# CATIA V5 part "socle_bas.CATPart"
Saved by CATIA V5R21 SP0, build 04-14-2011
Part number: socle_bas
Revision: A
Nomenclature: 2
Material "Blanc": density 7860 kg/m3, Young's modulus 2e+11 Pa, Poisson ratio 0.266
Bounding box of the stored display mesh (mm): x -22 to 22, y -42.5 to 42.5, z -36 to 0
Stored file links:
  C:\Users\Olivier\Desktop\redaction CATIA (local)\CATIA\DONNEES\Exercice assemblage 1 (chassis et socle)\socle_bas.CATPart
  C:\Program Files\Dassault Systemes\B21\win_b64\startup\materials\French\Catalog.CATMaterial
  C:\Users\Olivier\Desktop\redaction CATIA (local)\pompe à moteur de ventilation refait\Pompe_a_moteur_de_ventilation.CATProduct
  C:\Users\Olivier\Desktop\redaction CATIA (local)\pompe à moteur de ventilation refait\Ecrou a collerette M5.CATPart
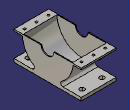
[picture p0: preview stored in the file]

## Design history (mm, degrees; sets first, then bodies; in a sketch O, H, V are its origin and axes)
Body1 (main body), material "Blanc"
  Sketch1 on yz-plane, origin (0, 0, 0), H (0, 1, 0), V (0, 0, 1)
    arc A1 centre (0, 0) radius 8 from (-8, 0) to (8, 0) ccw
    arc A2 centre (0, 0) radius 32 from (17.9163, -26.5143) to (31.9374, -2) ccw
    point P1 (-42.5, 0)
    line L1 (-42.5, 0) -> (-8, 0)
    point P2 (42.5, 0)
    line L2 (-42.5, 0) -> (-42.5, -2)
    line L3 (-42.5, -2) -> (-31.9374, -2)
    point P4 (-31.9374, -2)
    line L4 (42.5, 0) -> (42.5, -2)
    point P5 (42.5, -2)
    line L5 (42.5, -2) -> (31.9374, -2)
    line L6 (-42.5, -36) -> (42.5, -36)
    construction line L7 (-42.5, 0) -> (-42.5, -36)
    construction line L8 (42.5, 0) -> (42.5, -36)
    line L9 (-42.5, -36) -> (-42.5, -32)
    line L10 (42.5, -36) -> (42.5, -32)
    point P10 (42.5, -32)
    line L11 (-19.5959, -32) -> (-42.5, -32)
    arc A3 centre (-19.5959, -29) radius 3 from (-17.9163, -26.5143) to (-19.5959, -32) cw
    point P13 (0, -32)
    line L12 (42.5, -32) -> (19.5959, -32)
    point P15 (0, -32)
    arc A4 centre (19.5959, -29) radius 3 from (17.9163, -26.5143) to (19.5959, -32) ccw
    arc A5 centre (0, 0) radius 32 from (-31.9374, -2) to (-17.9163, -26.5143) ccw
    point P20 (8, 0)
    line L13 (8, 0) -> (42.5, 0)
    radius A1 = 8
    radius A2 = 32
    distance P1 P2 = 85
    length L2 = 2
    distance L1 L6 = 36
    length L9 = 4
    radius A3 = 3
    radius A4 = 3
    coincidence: P1 H, P4 A2, P5 L3, L11 P10, P15 A2, P13 P15, A2 P13, L12 P15, A2 A5, L1 P20, L1 L13
    horizontal: L1 H, L3 H, L5 H, L13 H
    symmetry: P1 P2 V
    vertical: L2 V, L4 V, L9 V, L10 V
    perpendicularity: L7 L1, L7 L6, L8 L1, L8 L6
    tangency: L11 A2, A3 A2, A3 L11, L12 A2, A4 A2, A4 L12
  Pad1: profile Sketch1, direction (1, 0, 0), length 22, mirrored extent
  Sketch2 on yz-plane, origin (0, 0, 0), H (0, 1, 0), V (0, 0, 1)
    circle A1 centre (0, 0) radius 31
    radius A1 = 31
  Pocket1: profile Sketch2, direction (-1, 0, 0), length 21, mirrored extent
  Sketch3 on face of Pad1 from Sketch1.L1, origin (-10.3446, -37.6937, 0), H (1, 0, 0), V (0, 1, 0)
    point P1 (-4.6554, 1.6937)
    reference projected line E1 through (0, 37.6937) direction (1, 0) from axis of face of Pocket1 from Sketch2.A1
    reference intersected line E2 through (10.3446, 0) direction (0, 1) from yz-plane
    distance P1 E1 = 36
    distance E2 P1 = 15
  Hole1: placed by Sketch3, at (-15, -36, 0) direction (0, 0, -1), diameter 3, through (limit type 6)
  RectPattern1: of Hole1, direction 1 instances 2, spacing 72, along edge [start face of Pad1 | face of Pad1 from Sketch1.L1] reversed, direction 2 instances 3, spacing 15, along edge [face of Pad1 from Sketch1.L2 | face of Pad1 from Sketch1.L1]
  Sketch4 on face of Pad1 from Sketch1.L6, origin (13.0733, -32.8372, -36), H (1, 0, 0), V (0, -1, 0)
    point P1 (-0.5733, 1.1628)
    reference projected line E1 through (0, -32.8372) direction (1, 0) from axis of face of Pad1 from Sketch1.A5
    reference intersected line E2 through (-13.0733, 0) direction (0, 1) from yz-plane
    distance P1 E1 = 34
    distance P1 E2 = 12.5
  Hole2: placed by Sketch4, at (12.5, -34, -36) direction (0, 0, 1), diameter 6, through (limit type 6)
  RectPattern2: of Hole2, direction 1 instances 2, spacing 25, along edge [face of Pad1 from Sketch1.L9 | face of Pad1 from Sketch1.L11] reversed, direction 2 instances 2, spacing 68, along edge [face of Pad1 from Sketch1.L6 | end face of Pad1]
